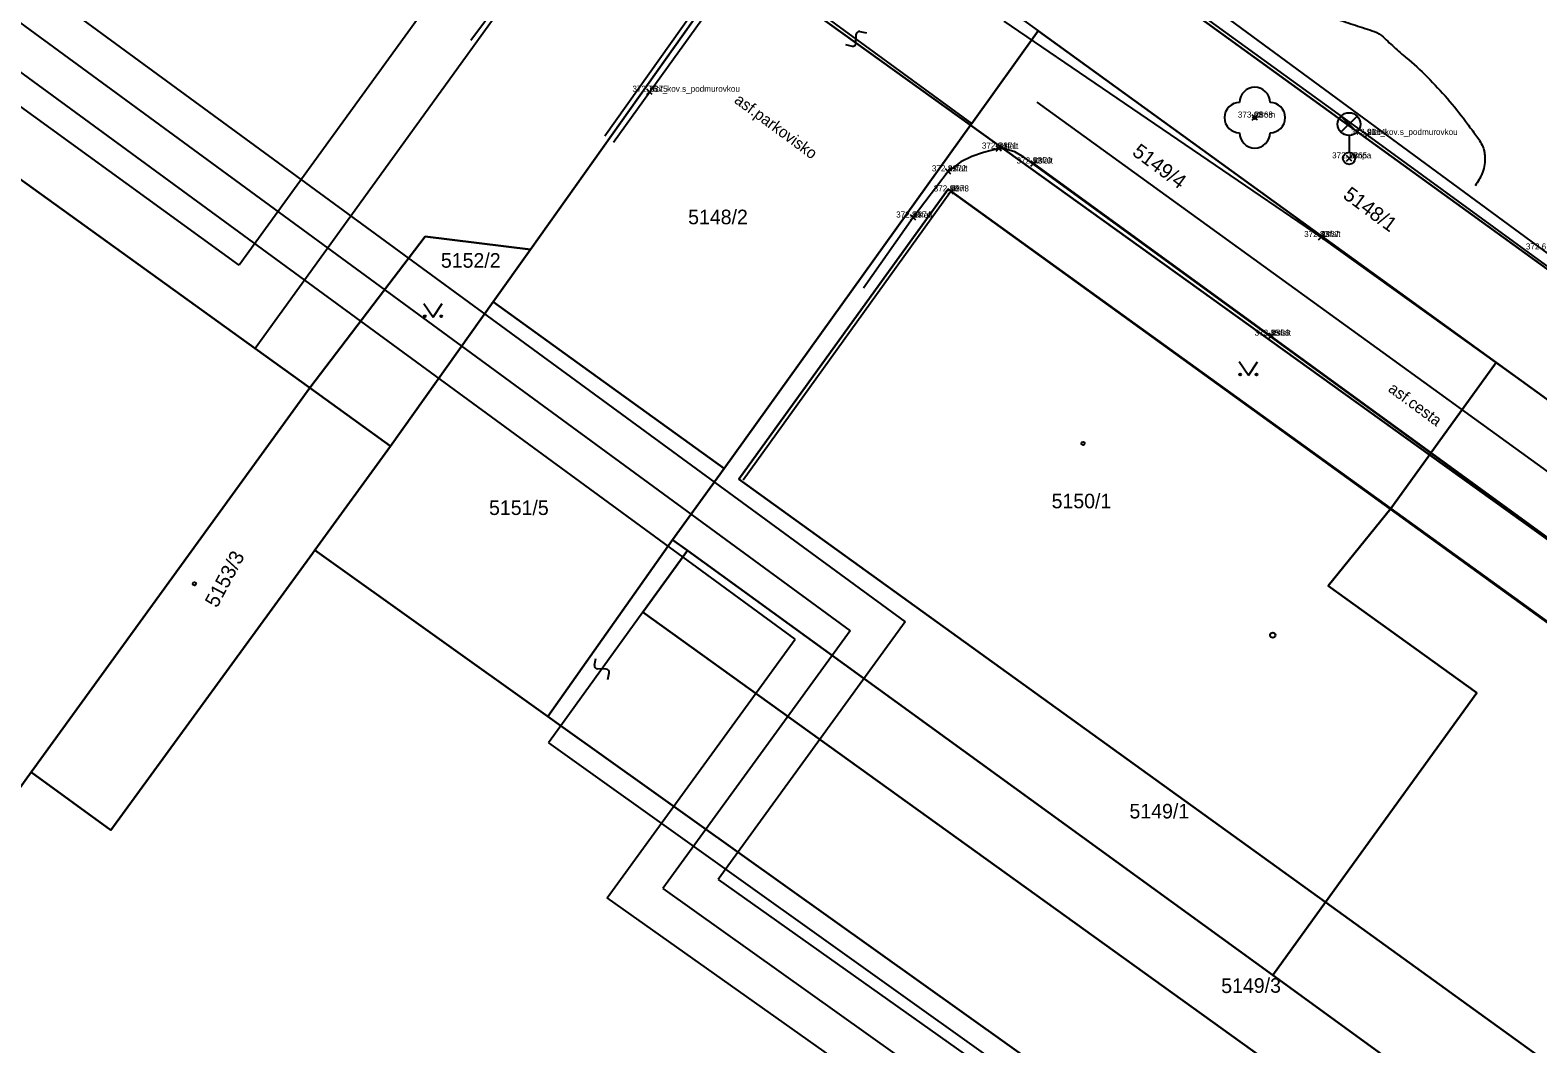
# Model space of a CAD drawing. Extents: x -400488 to -400124, y -1251493 to -1251223.
# Drawn here: x -400364.05 to -400314.45, y -1251406.21 to -1251372.84 of the extents above; entities that cross this region are included whole.
import ezdxf

# ---------------------------------------------------------------- set-up
doc = ezdxf.new("R2010")
doc.units = 0
for name, color, linetype in [('Level 20', 7, 'Continuous'), ('Level 21', 7, 'Continuous'), ('Level 22', 7, 'Continuous'), ('Level 23', 7, 'Continuous'), ('Level 32', 7, 'Continuous'), ('Level 34', 7, 'Continuous'), ('Level 35', 7, 'Continuous'), ('Level 36', 7, 'Continuous'), ('Level 49', 7, 'Continuous'), ('Level 53', 7, 'Continuous'), ('Level 63', 7, 'Continuous')]:
    doc.layers.add(name, color=color, linetype=linetype)

msp = doc.modelspace()

# ---------------------------------------------------------------- linework, layer by layer
at = {"layer": 'Level 20'}
for p, q in [((-400343.758, -1251374.958), (-400343.582, -1251374.782)), ((-400343.582, -1251374.958), (-400343.758, -1251374.782)), ((-400323.848, -1251375.808), (-400323.672, -1251375.632)), ((-400323.672, -1251375.808), (-400323.848, -1251375.632)), ((-400320.148, -1251376.378), (-400319.972, -1251376.202)), ((-400319.972, -1251376.378), (-400320.148, -1251376.202)), ((-400332.268, -1251376.828), (-400332.092, -1251376.652)), ((-400332.092, -1251376.828), (-400332.268, -1251376.652)), ((-400331.128, -1251377.318), (-400330.952, -1251377.142)), ((-400330.952, -1251377.318), (-400331.128, -1251377.142)), ((-400320.748, -1251377.148), (-400320.572, -1251376.972)), ((-400320.572, -1251377.148), (-400320.748, -1251376.972)), ((-400333.938, -1251377.578), (-400333.762, -1251377.402)), ((-400333.762, -1251377.578), (-400333.938, -1251377.402)), ((-400333.848, -1251378.238), (-400333.672, -1251378.062)), ((-400333.672, -1251378.238), (-400333.848, -1251378.062)), ((-400335.088, -1251379.098), (-400334.912, -1251378.922)), ((-400334.912, -1251379.098), (-400335.088, -1251378.922)), ((-400321.668, -1251379.738), (-400321.492, -1251379.562)), ((-400321.492, -1251379.738), (-400321.668, -1251379.562)), ((-400323.298, -1251382.988), (-400323.122, -1251382.812)), ((-400323.122, -1251382.988), (-400323.298, -1251382.812))]:
    msp.add_line(p, q, dxfattribs=at)
at = {"layer": 'Level 32'}
for points in [[(-400340.9, -1251370.35), (-400341.72, -1251369.6), (-400344.98, -1251367.06), (-400349.554, -1251373.182)], [(-400313.44, -1251385.49), (-400321.58, -1251379.65), (-400332, -1251372.55)], [(-400298.195, -1251398.906), (-400330.918, -1251375.214)], [(-400331.04, -1251377.23), (-400305.58, -1251395.77), (-400331.355, -1251377.021), (-400331.659, -1251376.849), (-400331.92, -1251376.772), (-400332.18, -1251376.74), (-400332.684, -1251376.866), (-400333.069, -1251377.004), (-400333.432, -1251377.178), (-400333.85, -1251377.49), (-400335, -1251379.01), (-400336.633, -1251381.335)]]:
    msp.add_lwpolyline(points, dxfattribs=at)
at = {"layer": 'Level 34'}
for points in [[(-400333.76, -1251378.15), (-400340.588, -1251387.651)], [(-400333.76, -1251378.15), (-400304.338, -1251399.434), (-400304.338, -1251399.434), (-400309.014, -1251405.829)]]:
    msp.add_lwpolyline(points, dxfattribs=at)
msp.add_circle((-400323.171, -1251392.755), 0.0875, dxfattribs=at)
at = {"layer": 'Level 35'}
msp.add_line((-400345.145, -1251376.318), (-400340.9, -1251370.35), dxfattribs=at)
for points in [[(-400330.938, -1251368.394), (-400330.78, -1251368.19), (-400329.16, -1251369.12), (-400314.31, -1251380.06), (-400302.65, -1251388.59)], [(-400311.61, -1251382.45), (-400320.06, -1251376.29), (-400329.68, -1251369.31)], [(-400344.859, -1251376.524), (-400340.57, -1251370.56), (-400340.62, -1251370.53), (-400340.9, -1251370.35)]]:
    msp.add_lwpolyline(points, dxfattribs=at)
at = {"layer": 'Level 36'}
for q in [(-400324.272, -1251383.757), (-400323.672, -1251383.757)]:
    msp.add_line((-400323.972, -1251384.207), q, dxfattribs=at)
for centre, radius in [((-400323.76, -1251375.72), 0.05), ((-400324.242, -1251384.177), 0.03), ((-400323.702, -1251384.177), 0.03)]:
    msp.add_circle(centre, radius, dxfattribs=at)
for centre, start, end in [((-400323.76, -1251375.22), 0, 180), ((-400324.26, -1251375.72), 90, 270), ((-400323.26, -1251375.72), 270, 90), ((-400323.76, -1251376.22), 180, 0)]:
    msp.add_arc(centre, 0.5, start, end, dxfattribs=at)
at = {"layer": 'Level 49'}
for points in [[(-400298.007, -1251373.633), (-400298.101, -1251373.657), (-400298.385, -1251373.715), (-400298.668, -1251373.698), (-400298.999, -1251373.598), (-400299.315, -1251373.468), (-400299.9, -1251373.106), (-400300.929, -1251372.15), (-400302.098, -1251370.777), (-400305.291, -1251366.626), (-400307.213, -1251363.775), (-400309.026, -1251360.802), (-400309.479, -1251359.989), (-400309.683, -1251359.57), (-400309.864, -1251359.138), (-400309.872, -1251359.107), (-400310.092, -1251357.753), (-400310.245, -1251356.389), (-400310.408, -1251355.025), (-400310.657, -1251353.672), (-400310.667, -1251353.649), (-400314.159, -1251348.989), (-400316.285, -1251346.155), (-400316.296, -1251346.134), (-400316.569, -1251345.318), (-400316.732, -1251344.464), (-400316.96, -1251343.625)], [(-400313.045, -1251380.55), (-400312.785, -1251380.273), (-400312.64, -1251380.146), (-400312.489, -1251380.025), (-400312.237, -1251379.858), (-400311.969, -1251379.724), (-400311.411, -1251379.516), (-400310.791, -1251379.385), (-400310.166, -1251379.309), (-400309.54, -1251379.247), (-400308.917, -1251379.155), (-400308.899, -1251379.15), (-400308.83, -1251379.101), (-400308.767, -1251379.048), (-400308.656, -1251378.931), (-400308.494, -1251378.661), (-400308.397, -1251378.361), (-400308.352, -1251378.054), (-400308.348, -1251377.725), (-400308.396, -1251377.399), (-400308.564, -1251376.806), (-400309.119, -1251375.433), (-400309.758, -1251374.051), (-400310.53, -1251372.737), (-400310.751, -1251372.429), (-400310.982, -1251372.131), (-400311.485, -1251371.569), (-400315.465, -1251367.634), (-400317.117, -1251365.966), (-400317.595, -1251365.311), (-400317.789, -1251364.95), (-400317.971, -1251364.582), (-400317.985, -1251364.548), (-400317.986, -1251364.544), (-400318.112, -1251363.714), (-400319.064, -1251357.286), (-400319.758, -1251356.341)], [(-400324.716, -1251371.623), (-400323.433, -1251371.838), (-400322.167, -1251372.141), (-400320.916, -1251372.519), (-400320.294, -1251372.733), (-400319.674, -1251372.961), (-400319.653, -1251372.973), (-400319.44, -1251373.157), (-400319.234, -1251373.346), (-400319.028, -1251373.535), (-400318.817, -1251373.717), (-400318.792, -1251373.737), (-400318.081, -1251374.386), (-400317.423, -1251375.095), (-400316.828, -1251375.834), (-400316.558, -1251376.206), (-400316.309, -1251376.574), (-400316.225, -1251376.785), (-400316.204, -1251376.896), (-400316.191, -1251377.006), (-400316.27, -1251377.521), (-400316.321, -1251377.641), (-400316.378, -1251377.756), (-400316.515, -1251377.967)]]:
    msp.add_spline(points, degree=3, dxfattribs=at)
at = {"layer": 'Level 53'}
for p, q in [((-400320.925, -1251376.2), (-400320.395, -1251375.67)), ((-400320.395, -1251375.67), (-400320.925, -1251376.2)), ((-400320.395, -1251376.2), (-400320.925, -1251375.67)), ((-400320.66, -1251376.31), (-400320.66, -1251376.86))]:
    msp.add_line(p, q, dxfattribs=at)
for centre, radius in [((-400320.66, -1251375.935), 0.375), ((-400320.66, -1251377.06), 0.2)]:
    msp.add_circle(centre, radius, dxfattribs=at)
at = {"layer": 'Level 63'}
for p, q in [((-400382.94, -1251357.38), (-400335.26, -1251392.32)), ((-400382.66, -1251359.2), (-400337.07, -1251392.61)), ((-400338.88, -1251392.89), (-400382.38, -1251361.02)), ((-400298.43, -1251392.08), (-400336.35, -1251364.63)), ((-400336.35, -1251364.63), (-400298.43, -1251392.08)), ((-400346.58, -1251365.95), (-400357.17, -1251380.58)), ((-400344.99, -1251367.18), (-400356.64, -1251383.32)), ((-400338.44, -1251367.39), (-400330.89, -1251372.86)), ((-400357.17, -1251380.58), (-400372.54, -1251369.43)), ((-400340.77, -1251370.46), (-400347.59, -1251380.06)), ((-400347.59, -1251380.06), (-400340.77, -1251370.46)), ((-400333.11, -1251375.97), (-400340.77, -1251370.46)), ((-400340.77, -1251370.46), (-400333.11, -1251375.97)), ((-400333.07, -1251375.91), (-400340.68, -1251370.34)), ((-400336.881, -1251373.272), (-400336.869, -1251372.978)), ((-400336.748, -1251372.884), (-400336.53, -1251372.932)), ((-400333.07, -1251375.91), (-400330.89, -1251372.86)), ((-400330.89, -1251372.86), (-400333.07, -1251375.91)), ((-400330.89, -1251372.86), (-400315.82, -1251383.78)), ((-400315.82, -1251383.78), (-400330.89, -1251372.86)), ((-400337.22, -1251373.318), (-400337.002, -1251373.366)), ((-400356.64, -1251383.32), (-400369.4, -1251374.13)), ((-400369.4, -1251374.13), (-400356.64, -1251383.32)), ((-400341.22, -1251387.27), (-400333.11, -1251375.97)), ((-400333.11, -1251375.97), (-400341.22, -1251387.27)), ((-400333.11, -1251375.97), (-400333.07, -1251375.91)), ((-400333.07, -1251375.91), (-400333.11, -1251375.97)), ((-400318.01, -1251386.82), (-400333.11, -1251375.97)), ((-400333.11, -1251375.97), (-400318.01, -1251386.82)), ((-400340.73, -1251387.62), (-400333.85, -1251378.08)), ((-400333.85, -1251378.08), (-400340.73, -1251387.62)), ((-400333.85, -1251378.08), (-400319.29, -1251388.59)), ((-400319.29, -1251388.59), (-400333.85, -1251378.08)), ((-400354.85, -1251384.61), (-400351.05, -1251379.63)), ((-400351.05, -1251379.63), (-400354.85, -1251384.61)), ((-400351.05, -1251379.63), (-400347.59, -1251380.06)), ((-400347.59, -1251380.06), (-400351.05, -1251379.63)), ((-400347.59, -1251380.06), (-400348.81, -1251381.78)), ((-400348.81, -1251381.78), (-400347.59, -1251380.06)), ((-400348.81, -1251381.78), (-400352.19, -1251386.53)), ((-400352.19, -1251386.53), (-400348.81, -1251381.78)), ((-400351.09, -1251381.84), (-400350.79, -1251382.29)), ((-400350.79, -1251382.29), (-400350.49, -1251381.84)), ((-400348.81, -1251381.78), (-400345.85, -1251383.92)), ((-400345.85, -1251383.92), (-400348.81, -1251381.78)), ((-400354.85, -1251384.61), (-400356.64, -1251383.32)), ((-400356.64, -1251383.32), (-400354.85, -1251384.61)), ((-400345.85, -1251383.92), (-400341.22, -1251387.27)), ((-400341.22, -1251387.27), (-400345.85, -1251383.92)), ((-400315.82, -1251383.78), (-400318.01, -1251386.82)), ((-400318.01, -1251386.82), (-400315.82, -1251383.78)), ((-400315.82, -1251383.78), (-400299.2, -1251395.82)), ((-400299.2, -1251395.82), (-400315.82, -1251383.78)), ((-400364.01, -1251397.27), (-400354.85, -1251384.61)), ((-400354.85, -1251384.61), (-400364.01, -1251397.27)), ((-400354.85, -1251384.61), (-400352.19, -1251386.53)), ((-400352.19, -1251386.53), (-400354.85, -1251384.61)), ((-400352.19, -1251386.53), (-400354.68, -1251389.96)), ((-400354.68, -1251389.96), (-400352.19, -1251386.53)), ((-400354.68, -1251389.96), (-400352.19, -1251386.53)), ((-400318.06, -1251386.89), (-400319.29, -1251388.59)), ((-400319.29, -1251388.59), (-400318.06, -1251386.89)), ((-400318.01, -1251386.82), (-400318.06, -1251386.89)), ((-400318.06, -1251386.89), (-400318.01, -1251386.82)), ((-400304.57, -1251396.48), (-400318.01, -1251386.82)), ((-400318.01, -1251386.82), (-400304.57, -1251396.48)), ((-400341.22, -1251387.27), (-400342.91, -1251389.62)), ((-400342.91, -1251389.62), (-400341.22, -1251387.27)), ((-400321.44, -1251401.55), (-400340.73, -1251387.62)), ((-400340.73, -1251387.62), (-400321.44, -1251401.55)), ((-400321.35, -1251391.13), (-400319.29, -1251388.59)), ((-400319.29, -1251388.59), (-400321.35, -1251391.13)), ((-400319.29, -1251388.59), (-400304.29, -1251399.42)), ((-400304.29, -1251399.42), (-400319.29, -1251388.59)), ((-400347.02, -1251395.43), (-400342.91, -1251389.62)), ((-400342.91, -1251389.62), (-400347.02, -1251395.43)), ((-400342.91, -1251389.62), (-400342.42, -1251389.97)), ((-400342.42, -1251389.97), (-400342.91, -1251389.62)), ((-400354.76, -1251390.07), (-400361.39, -1251399.18)), ((-400361.39, -1251399.18), (-400354.76, -1251390.07)), ((-400361.39, -1251399.18), (-400354.76, -1251390.07)), ((-400354.68, -1251389.96), (-400354.76, -1251390.07)), ((-400354.76, -1251390.07), (-400354.68, -1251389.96)), ((-400354.76, -1251390.07), (-400354.68, -1251389.96)), ((-400354.68, -1251389.96), (-400347.02, -1251395.43)), ((-400347.02, -1251395.43), (-400354.68, -1251389.96)), ((-400342.42, -1251389.97), (-400343.89, -1251392)), ((-400343.89, -1251392), (-400342.42, -1251389.97)), ((-400342.42, -1251389.97), (-400323.17, -1251403.95)), ((-400323.17, -1251403.95), (-400342.42, -1251389.97)), ((-400316.46, -1251394.65), (-400321.35, -1251391.13)), ((-400321.35, -1251391.13), (-400316.46, -1251394.65)), ((-400343.89, -1251392), (-400346.59, -1251395.74)), ((-400343.89, -1251392), (-400312.09, -1251414.87)), ((-400312.09, -1251414.87), (-400343.89, -1251392)), ((-400337.07, -1251392.61), (-400343.23, -1251401.1)), ((-400335.26, -1251392.32), (-400341.41, -1251400.8)), ((-400345.06, -1251401.4), (-400338.88, -1251392.89)), ((-400345.481, -1251393.743), (-400345.433, -1251393.525)), ((-400345.093, -1251393.876), (-400345.387, -1251393.864)), ((-400345.047, -1251394.215), (-400344.999, -1251393.997)), ((-400321.44, -1251401.55), (-400316.46, -1251394.65)), ((-400316.46, -1251394.65), (-400321.44, -1251401.55)), ((-400346.59, -1251395.74), (-400347.02, -1251395.43)), ((-400347.02, -1251395.43), (-400346.59, -1251395.74)), ((-400346.59, -1251395.74), (-400346.99, -1251396.3)), ((-400346.59, -1251395.74), (-400346.99, -1251396.3)), ((-400314.7, -1251418.49), (-400346.59, -1251395.74)), ((-400346.59, -1251395.74), (-400314.7, -1251418.49)), ((-400346.99, -1251396.3), (-400316.83, -1251417.85)), ((-400346.99, -1251396.3), (-400316.83, -1251417.85)), ((-400364.01, -1251397.27), (-400370.19, -1251405.8)), ((-400370.19, -1251405.8), (-400364.01, -1251397.27)), ((-400361.39, -1251399.18), (-400364.01, -1251397.27)), ((-400364.01, -1251397.27), (-400361.39, -1251399.18)), ((-400364.01, -1251397.27), (-400361.39, -1251399.18)), ((-400341.41, -1251400.8), (-400300.81, -1251429.57)), ((-400300.27, -1251433.14), (-400345.06, -1251401.4)), ((-400343.23, -1251401.1), (-400335.53, -1251406.59)), ((-400321.44, -1251401.55), (-400323.17, -1251403.95)), ((-400323.17, -1251403.95), (-400321.44, -1251401.55)), ((-400311.14, -1251408.98), (-400321.44, -1251401.55)), ((-400321.44, -1251401.55), (-400311.14, -1251408.98)), ((-400323.17, -1251403.95), (-400310.73, -1251412.98)), ((-400310.73, -1251412.98), (-400323.17, -1251403.95))]:
    msp.add_line(p, q, dxfattribs=at)
for centre, radius in [((-400351.06, -1251382.26), 0.03), ((-400350.52, -1251382.26), 0.03), ((-400329.41, -1251386.446), 0.054), ((-400358.64, -1251391.066), 0.054)]:
    msp.add_circle(centre, radius, dxfattribs=at)
for centre, start, end in [((-400336.981, -1251373.268), 257.753, 357.7631), ((-400336.769, -1251372.982), 77.7527, 177.7631), ((-400345.383, -1251393.764), 167.7527, 267.7631), ((-400345.097, -1251393.976), 347.753, 87.7631)]:
    msp.add_arc(centre, 0.1, start, end, dxfattribs=at)

# ---------------------------------------------------------------- texts
at = {"layer": 'Level 21'}
for s, p in [('2375', (-400343.67, -1251374.87)), ('2368', (-400323.76, -1251375.72)), ('2364', (-400320.06, -1251376.29)), ('2371', (-400332.18, -1251376.74)), ('2370', (-400331.04, -1251377.23)), ('2365', (-400320.66, -1251377.06)), ('2372', (-400333.85, -1251377.49)), ('2373', (-400333.76, -1251378.15)), ('2374', (-400335, -1251379.01)), ('2367', (-400321.58, -1251379.65)), ('2366', (-400323.21, -1251382.9))]:
    msp.add_text(s, height=0.2, dxfattribs=at).set_placement(p)
at = {"layer": 'Level 22'}
for s, p in [('plot_kov.s_podmurovkou', (-400343.67, -1251374.87)), ('strom', (-400323.76, -1251375.72)), ('plot_kov.s_podmurovkou', (-400320.06, -1251376.29)), ('asfalt', (-400332.18, -1251376.74)), ('asfalt', (-400331.04, -1251377.23)), ('lampa', (-400320.66, -1251377.06)), ('asfalt', (-400333.85, -1251377.49)), ('dom', (-400333.76, -1251378.15)), ('asfalt', (-400335, -1251379.01)), ('asfalt', (-400321.58, -1251379.65)), ('asfalt', (-400323.21, -1251382.9))]:
    msp.add_text(s, height=0.2, dxfattribs=at).set_placement(p)
at = {"layer": 'Level 23'}
for s, p in [('372.76', (-400344.233, -1251374.87)), ('373.03', (-400324.318, -1251375.72)), ('372.91', (-400320.593, -1251376.29)), ('372.84', (-400332.738, -1251376.74)), ('372.82', (-400331.598, -1251377.23)), ('372.78', (-400321.218, -1251377.06)), ('372.81', (-400334.383, -1251377.49)), ('372.86', (-400334.323, -1251378.15)), ('372.84', (-400335.558, -1251379.01)), ('372.83', (-400322.138, -1251379.65)), ('372.61', (-400314.843, -1251380.06)), ('372.85', (-400323.769, -1251382.9))]:
    msp.add_text(s, height=0.2, dxfattribs=at).set_placement(p)
at = {"layer": 'Level 32'}
for s, p in [('asf.parkovisko', (-400340.912, -1251375.207)), ('asf.cesta', (-400319.401, -1251384.709))]:
    msp.add_text(s, height=0.375, rotation=323.6458, dxfattribs=at).set_placement(p)
at = {"layer": 'Level 63'}
for s, rotation, p in [('5149/4', 323.6022, (-400327.824, -1251376.927)), ('5148/1', 323.5818, (-400320.892, -1251378.344)), ('5153/3', 61.88, (-400357.9, -1251391.882)), ('5149/1', 0.01, (-400327.883, -1251398.79)), ('5149/3', 0.33, (-400324.863, -1251404.537))]:
    msp.add_text(s, height=0.48, rotation=rotation, dxfattribs=at).set_placement(p)
for s, p in [('5148/2', (-400342.4, -1251379.23)), ('5152/2', (-400350.533, -1251380.661)), ('5150/1', (-400330.444, -1251388.58)), ('5151/5', (-400348.95, -1251388.8))]:
    msp.add_text(s, height=0.48, dxfattribs=at).set_placement(p)

doc.saveas('drawing.dxf')
